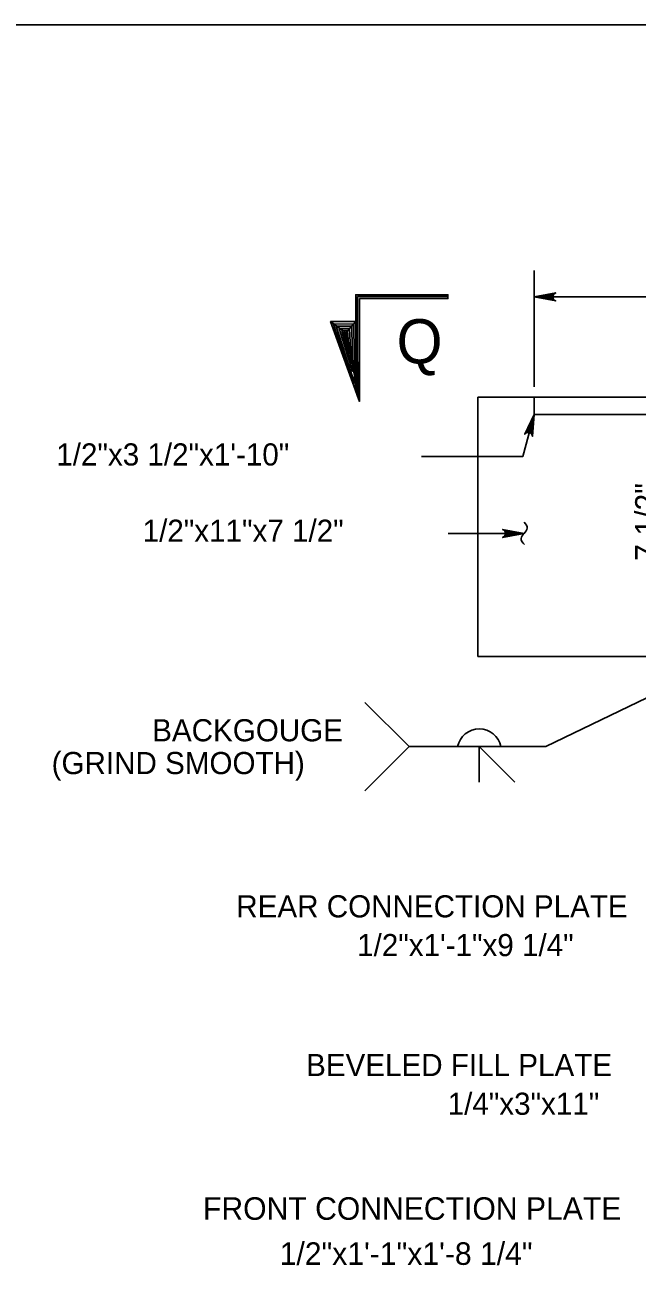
# Model space of a CAD drawing. Extents: x 632007860 to 635435983, y 295418622 to 297794622.
# Drawn here: x 634113990 to 634198331, y 295826880 to 295997622 of the extents above; entities that cross this region are included whole.
import ezdxf

# ---------------------------------------------------------------- set-up
doc = ezdxf.new("R2010")
doc.units = 0
for name, color, linetype in [('1', 7, 'Continuous'), ('S-DETL-DIMS', 7, 'Continuous'), ('S-DETL-T120', 7, 'Continuous'), ('S-DETL-T240', 7, 'Continuous'), ('S-STEL', 7, 'Continuous')]:
    doc.layers.add(name, color=color, linetype=linetype)

msp = doc.modelspace()

# ---------------------------------------------------------------- linework, layer by layer
at = {"layer": '1'}
msp.add_line((633729860, 295997622), (634515860, 295997622), dxfattribs=at)
at = {"layer": 'S-DETL-DIMS'}
for p, q in [((634184143, 295963819), (634184143, 295947784)), ((634184143, 295960169), (634227006, 295960169)), ((634182593, 295938200), (634184143, 295943986)), ((634168620, 295938200), (634182593, 295938200)), ((634172313, 295927617), (634182759, 295927617)), ((634227006, 295918226), (634185729, 295898258)), ((634185729, 295898258), (634166933, 295898258)), ((634179572, 295898258), (634173598, 295898258))]:
    msp.add_line(p, q, dxfattribs=at)
msp.add_lwpolyline([(634172262, 295959940), (634172262, 295960469), (634159562, 295960469), (634159562, 295956765), (634156095, 295956765), (634160091, 295945786), (634160091, 295959940)], close=True, dxfattribs=at)
for points in [[(634172262, 295960204), (634159827, 295960204), (634159827, 295946513), (634160091, 295945786), (634160091, 295959940), (634172262, 295959940), (634172262, 295960469), (634159562, 295960469), (634159562, 295947240), (634156095, 295956765), (634159562, 295956765), (634160091, 295945786), (634156521, 295956424), (634159307, 295956447), (634159399, 295948315), (634156888, 295956137), (634159009, 295956137), (634159101, 295949944), (634157266, 295955839), (634158688, 295955827), (634158929, 295951022), (634157667, 295955552), (634158424, 295955541), (634158677, 295952444), (634157931, 295955300), (634158252, 295955265), (634158447, 295953580), (634158090, 295955293), (634156095, 295956765), (634159562, 295956765), (634158252, 295955265), (634160091, 295945786)], [(634184143, 295960169), (634187102, 295959614), (634186988, 295959693), (634186874, 295959772), (634186816, 295959871), (634186757, 295959970), (634186740, 295960069), (634186723, 295960169), (634186740, 295960268), (634186757, 295960367), (634186816, 295960466), (634186874, 295960565), (634186988, 295960644), (634187102, 295960723), (634184143, 295960169), (634186988, 295960644), (634186874, 295960565), (634184143, 295960169), (634186816, 295960466), (634186757, 295960367), (634184143, 295960169), (634186740, 295960268), (634186723, 295960169), (634184143, 295960169), (634186740, 295960069), (634186757, 295959970), (634184143, 295960169), (634186816, 295959871), (634186874, 295959772), (634184143, 295960169), (634186988, 295959693)], [(634184143, 295943986), (634182841, 295941271), (634182947, 295941360), (634183053, 295941450), (634183164, 295941481), (634183275, 295941512), (634183375, 295941503), (634183475, 295941494), (634183567, 295941452), (634183658, 295941410), (634183739, 295941327), (634183820, 295941245), (634183866, 295941114), (634183913, 295940984), (634184143, 295943986), (634183866, 295941114), (634183820, 295941245), (634184143, 295943986), (634183739, 295941327), (634183658, 295941410), (634184143, 295943986), (634183567, 295941452), (634183475, 295941494), (634184143, 295943986), (634183375, 295941503), (634183275, 295941512), (634184143, 295943986), (634183164, 295941481), (634183053, 295941450), (634184143, 295943986), (634182947, 295941360)], [(634182759, 295927617), (634179800, 295928172), (634179914, 295928093), (634180028, 295928014), (634180087, 295927915), (634180145, 295927815), (634180162, 295927716), (634180179, 295927617), (634180162, 295927518), (634180145, 295927419), (634180087, 295927319), (634180028, 295927220), (634179914, 295927141), (634179800, 295927062), (634182759, 295927617), (634179914, 295927141), (634180028, 295927220), (634182759, 295927617), (634180087, 295927319), (634180145, 295927419), (634182759, 295927617), (634180162, 295927518), (634180179, 295927617), (634182759, 295927617), (634180162, 295927716), (634180145, 295927815), (634182759, 295927617), (634180087, 295927915), (634180028, 295928014), (634182759, 295927617), (634179914, 295928093)], [(634160837, 295904354), (634166933, 295898258), (634160837, 295892162)], [(634176585, 295893382), (634176585, 295898258), (634181462, 295893382)]]:
    msp.add_lwpolyline(points, dxfattribs=at)
msp.add_arc((634176585, 295897649), 3048, 11.53462, 168.46538, dxfattribs=at)
msp.add_spline([(634182792, 295926070), (634182333, 295926927), (634183190, 295928315), (634182780, 295929160)], degree=3, dxfattribs=at)
at = {"layer": 'S-STEL'}
for p, q in [((634288915, 295946369), (634176405, 295946369)), ((634176405, 295946369), (634176405, 295910650)), ((634184143, 295946369), (634184143, 295943986)), ((634184143, 295943986), (634288915, 295943986)), ((634227006, 295910650), (634176405, 295910650))]:
    msp.add_line(p, q, dxfattribs=at)

# ---------------------------------------------------------------- texts
at = {"layer": 'S-DETL-T120'}
for s, height, p in [('  1/2"x3 1/2"x1\'-10"', 3048.01, (634116064, 295936958)), ('  1/2"x11"x7 1/2"', 3048.01, (634127956, 295926455)), ('BACKGOUGE', 3048, (634131533, 295898990)), ('(GRIND SMOOTH)', 3048.01, (634117685, 295894478)), ('REAR CONNECTION PLATE', 3048.01, (634143120, 295874753)), ('  1/2"x1\'-1"x9 1/4"', 3048.01, (634157495, 295869419)), ('BEVELED FILL PLATE', 3048.01, (634152731, 295852912)), ('  1/4"x3"x11"', 3048.01, (634169963, 295847578)), ('FRONT CONNECTION PLATE', 3102.17, (634138531, 295833128)), ('  1/2"x1\'-1"x1\'-8 1/4"', 3102.17, (634146787, 295826924))]:
    msp.add_text(s, height=height, dxfattribs=at).set_placement(p)
msp.add_text('7 1/2"', height=3102.2, rotation=90, dxfattribs=at).set_placement((634201148, 295923838))
at = {"layer": 'S-DETL-T240'}
msp.add_text('Q', height=6096, dxfattribs=at).set_placement((634165189, 295951003))

doc.saveas('drawing.dxf')
